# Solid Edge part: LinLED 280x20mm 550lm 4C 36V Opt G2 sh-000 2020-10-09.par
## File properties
Author: robert.pupel
Template: iso metric part.par
Last saved by: robert.pupel
Revision: 2
Application: Solid Edge
Gęstość: 0,000 kg/m^3
Dokładność: 0,990
Username: robert.pupel
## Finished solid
Body 1: solid body, 1182 faces, 3008 edges, 1872 vertices.
  Faces by surface: plane 600, cylinder 262, spline 192, cone 60, sphere 32, torus 20, spun 16
  Edges by curve: line 1772, curve on surface 648, circle 348, ellipse 132, spline 100, intersection 8
Bounding box of the edges (mm; curved faces can reach further): 280.000 x 4.450 x 20.000, from (-140, -3.45, -10) to (140, 1, 10).
Cylindrical faces by radius (mm): R0.2 x92, R0.2169 x12, R0.25 x24, R0.3373 x12, R0.4 x16, R0.4006 x4, R0.4008 x4, R0.525 x4, R0.6 x40, R1 x16, R1.1 x8, R1.2 x20, R2.15 x10
Conical faces (half-angle, radius in mm at the cone's reference point): 0.5 deg R0.5056 x8, 0.5 deg R1.0082 x8, 1 deg R0.5511 x4, 10 deg R0.2132 x8, 10 deg R0.4132 x8, 18.8604 deg R1.0669 x8, 27.363 deg R0.6214 x4, 45 deg R0.575 x4, 45 deg R0.625 x8
Toroidal faces (ring radius, tube radius in mm): R0.8 r0.2 x8, R0.8522 r0.3 x4, R0.9002 r0.2 x4, R0.9018 r0.2 x4
Spherical faces by radius (mm): R0.2 x24, R0.6 x8
Planar faces by outward normal: +x 65, +y 17, +z 62, -x 65, -y 85, -z 62, oblique 244
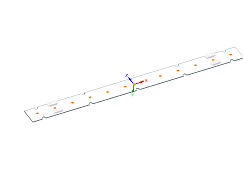
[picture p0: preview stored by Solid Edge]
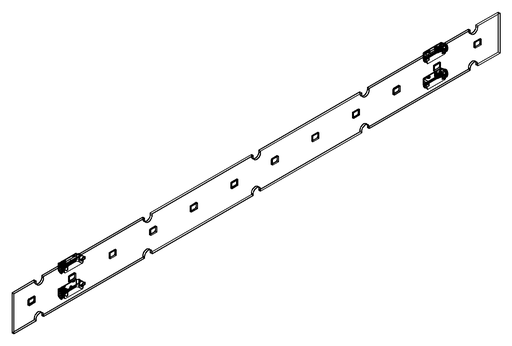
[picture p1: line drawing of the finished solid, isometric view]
